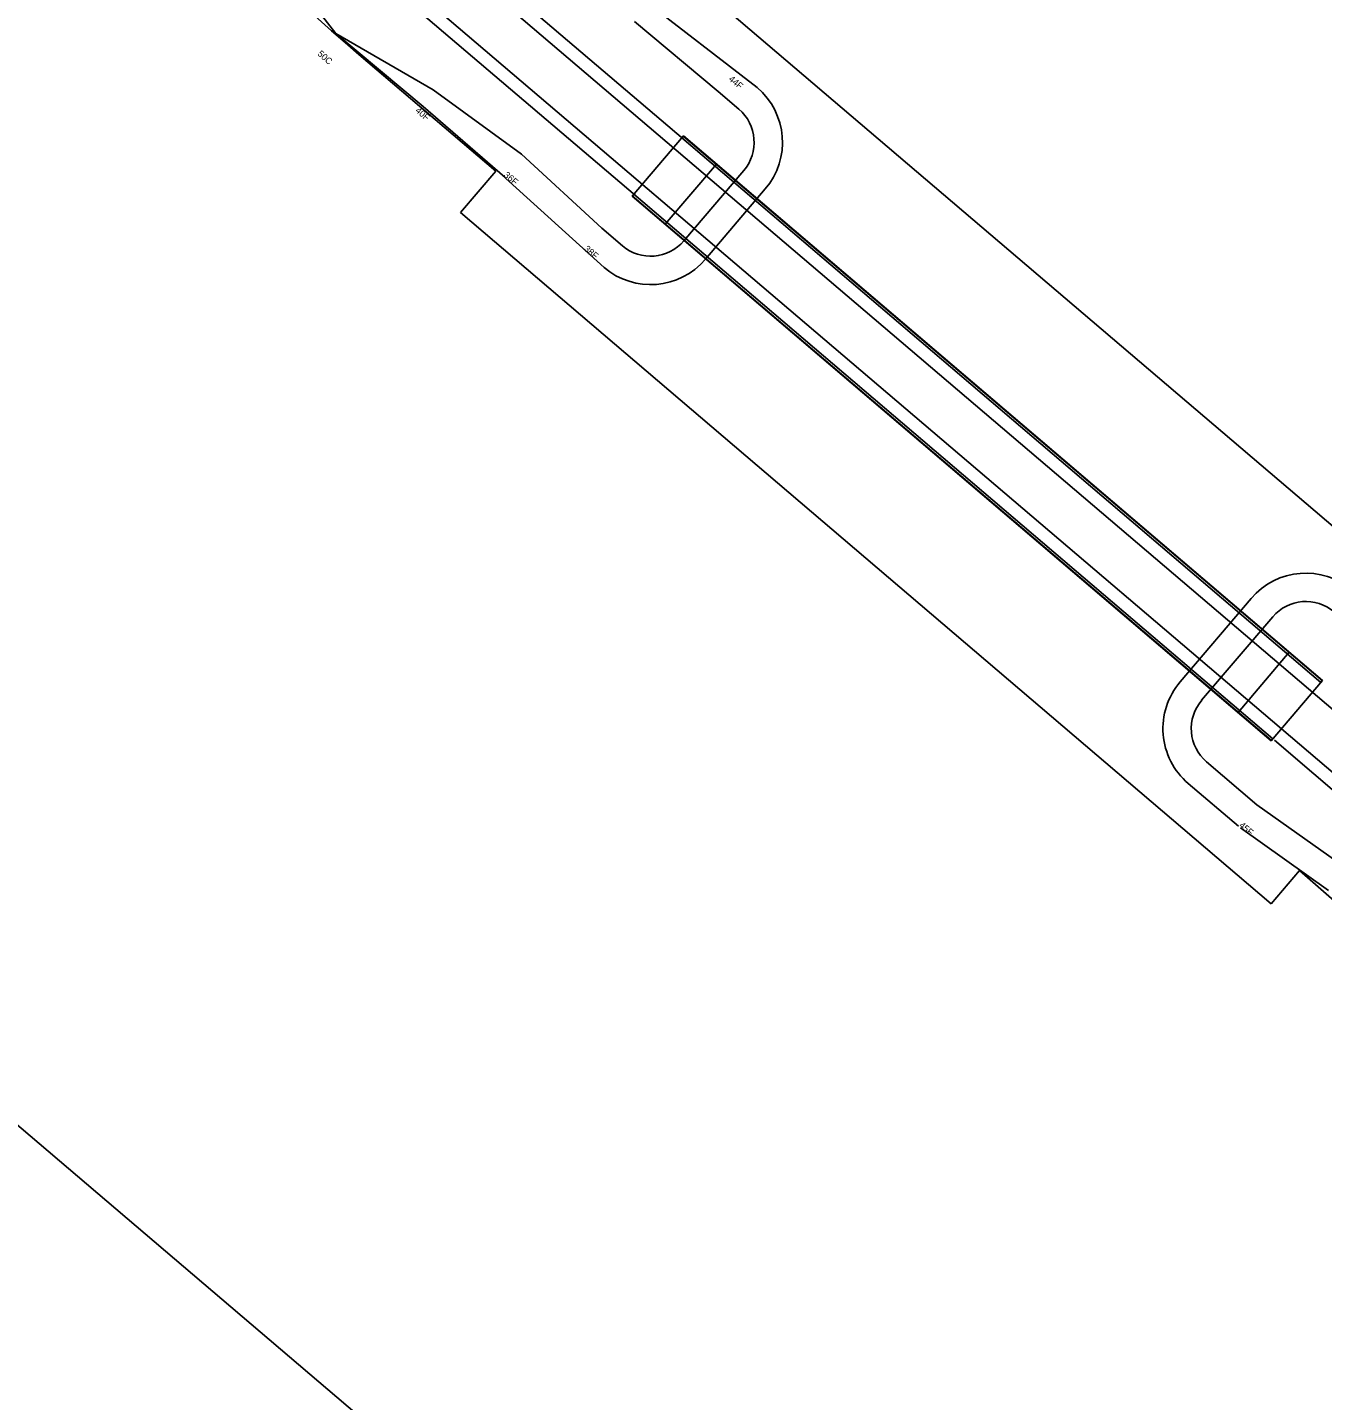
# Model space of a CAD drawing. Extents: x 2006539 to 2009039, y 1001971 to 1004377.
# Drawn here: x 2007375 to 2007969, y 1002537 to 1003166 of the extents above; entities that cross this region are included whole.
import ezdxf

# ---------------------------------------------------------------- set-up
doc = ezdxf.new("R2010")
doc.units = 0
for name, color, linetype in [('Default', 7, 'Continuous'), ('RD_PD_Bridge', 7, 'Continuous'), ('RD_PD_CstnLmt', 7, 'Continuous'), ('RD_PD_CstnLmt_TX', 7, 'Continuous'), ('RD_PD_DR_ErosCtrl', 7, 'Continuous'), ('RD_PD_Final_TrvlWay', 7, 'Continuous'), ('RD_PD_GR', 7, 'Continuous'), ('RD_PD_RW', 7, 'Continuous'), ('RD_Sketch2', 7, 'Continuous')]:
    doc.layers.add(name, color=color, linetype=linetype)

msp = doc.modelspace()

# ---------------------------------------------------------------- linework, layer by layer
at = {"layer": 'Default'}
msp.add_line((2007652.67, 1003089.06), (2007676.18, 1003116.66), dxfattribs=at)
at = {"layer": 'RD_PD_Bridge'}
for p, q in [((2007652.67, 1003089.06), (2007676.18, 1003116.66)), ((2007968.52, 1002866.13), (2007675.45, 1003115.8)), ((2007969.17, 1002866.89), (2007676.09, 1003116.56)), ((2007969.25, 1002866.99), (2007676.18, 1003116.66)), ((2007667.89, 1003076.09), (2007691.4, 1003103.69)), ((2007945.74, 1002839.39), (2007652.67, 1003089.06)), ((2007945.82, 1002839.49), (2007652.75, 1003089.16)), ((2007946.47, 1002840.25), (2007653.4, 1003089.92)), ((2007930.52, 1002852.36), (2007954.02, 1002879.96)), ((2007945.74, 1002839.39), (2007969.25, 1002866.99))]:
    msp.add_line(p, q, dxfattribs=at)
at = {"layer": 'RD_PD_CstnLmt'}
for p, q in [((2007483.94, 1003205.83), (2007516.74, 1003163.62)), ((2007653.79, 1003169.02), (2007692.14, 1003136.94)), ((2007516.74, 1003163.62), (2007561.45, 1003137.73)), ((2007561.45, 1003137.73), (2007601.96, 1003108.18)), ((2007692.14, 1003136.94), (2007701.58, 1003128.9)), ((2007601.96, 1003108.18), (2007638.77, 1003074.28)), ((2007676.4, 1003068.5), (2007703.84, 1003100.71)), ((2007638.77, 1003074.28), (2007648.21, 1003066.24)), ((2007913.83, 1002857.92), (2007946.42, 1002896.17)), ((2007939.15, 1002810.07), (2007916.09, 1002829.72)), ((2007939.15, 1002810.07), (2007979.54, 1002781.39))]:
    msp.add_line(p, q, dxfattribs=at)
for centre, start, end in [((2007688.61, 1003113.68), 319.57273, 49.57273), ((2007661.18, 1003081.47), 229.57273, 319.57273), ((2007961.64, 1002883.2), 49.57273, 139.57273), ((2007929.06, 1002844.95), 139.57273, 229.57273)]:
    msp.add_arc(centre, 20, start, end, dxfattribs=at)
at = {"layer": 'RD_PD_DR_ErosCtrl'}
for p, q in [((2007657.3, 1003179.54), (2007710.01, 1003138.8)), ((2007516.74, 1003163.62), (2007556.83, 1003130.08)), ((2007556.83, 1003130.08), (2007594.29, 1003097.68)), ((2007593.15, 1003098.61), (2007639.78, 1003056.35)), ((2007686.3, 1003060.07), (2007713.73, 1003092.28)), ((2007903.94, 1002866.35), (2007936.52, 1002904.6)), ((2007930.72, 1002800.18), (2007907.66, 1002819.83)), ((2007931.63, 1002799.47), (2007972.01, 1002770.79))]:
    msp.add_line(p, q, dxfattribs=at)
for centre, start, end in [((2007688.61, 1003113.68), 319.57273, 49.57273), ((2007661.18, 1003081.47), 229.57273, 319.57273), ((2007961.64, 1002883.2), 49.57273, 139.57273), ((2007929.06, 1002844.95), 139.57273, 229.57273)]:
    msp.add_arc(centre, 33, start, end, dxfattribs=at)
at = {"layer": 'RD_PD_Final_TrvlWay'}
for p, q in [((2007566.9, 1003200.38), (2008001.5, 1002830.16)), ((2007552.64, 1003183.64), (2007987.23, 1002813.41))]:
    msp.add_line(p, q, dxfattribs=at)
at = {"layer": 'RD_PD_GR'}
for p, q in [((2007570.79, 1003204.95), (2007676.21, 1003115.15)), ((2007654.16, 1003089.27), (2007548.75, 1003179.07)), ((2007983.34, 1002808.84), (2007947.23, 1002839.6))]:
    msp.add_line(p, q, dxfattribs=at)
at = {"layer": 'RD_PD_RW'}
for p, q in [((2007671.19, 1003195.62), (2008043, 1002878.88)), ((2007527.35, 1003153.95), (2007590.13, 1003100.46)), ((2007573.92, 1003081.43), (2007590.13, 1003100.46)), ((2007573.92, 1003081.43), (2007945.73, 1002764.69)), ((2007945.73, 1002764.69), (2007958.7, 1002779.92))]:
    msp.add_line(p, q, dxfattribs=at)
for centre, radius, start, end in [((2008085.61, 1003809.27), 860.87, 194.53337, 229.57273), ((2007371.33, 1002090.43), 905.75, 39.69899, 49.57273)]:
    msp.add_arc(centre, radius, start, end, dxfattribs=at)
at = {"layer": 'RD_Sketch2'}
msp.add_lwpolyline([(2006538.91, 1003372), (2008183.17, 1001971.28), (2009039.16, 1002976.1), (2007394.91, 1004376.83)], close=True, dxfattribs=at)

# ---------------------------------------------------------------- texts
at = {"layer": 'RD_PD_CstnLmt_TX'}
for s, rotation, p in [('50C', 318.61725, (2007508.14, 1003153.87)), ('44F', 319.57273, (2007696.68, 1003142.27)), ('40F', 319.57273, (2007553.02, 1003127.83)), ('36F', 319.57273, (2007593.53, 1003098.28)), ('38F', 319.57273, (2007630.34, 1003064.39)), ('45F', 319.57273, (2007930.72, 1002800.18))]:
    msp.add_text(s, height=3, rotation=rotation, dxfattribs=at).set_placement(p)

doc.saveas('drawing.dxf')
